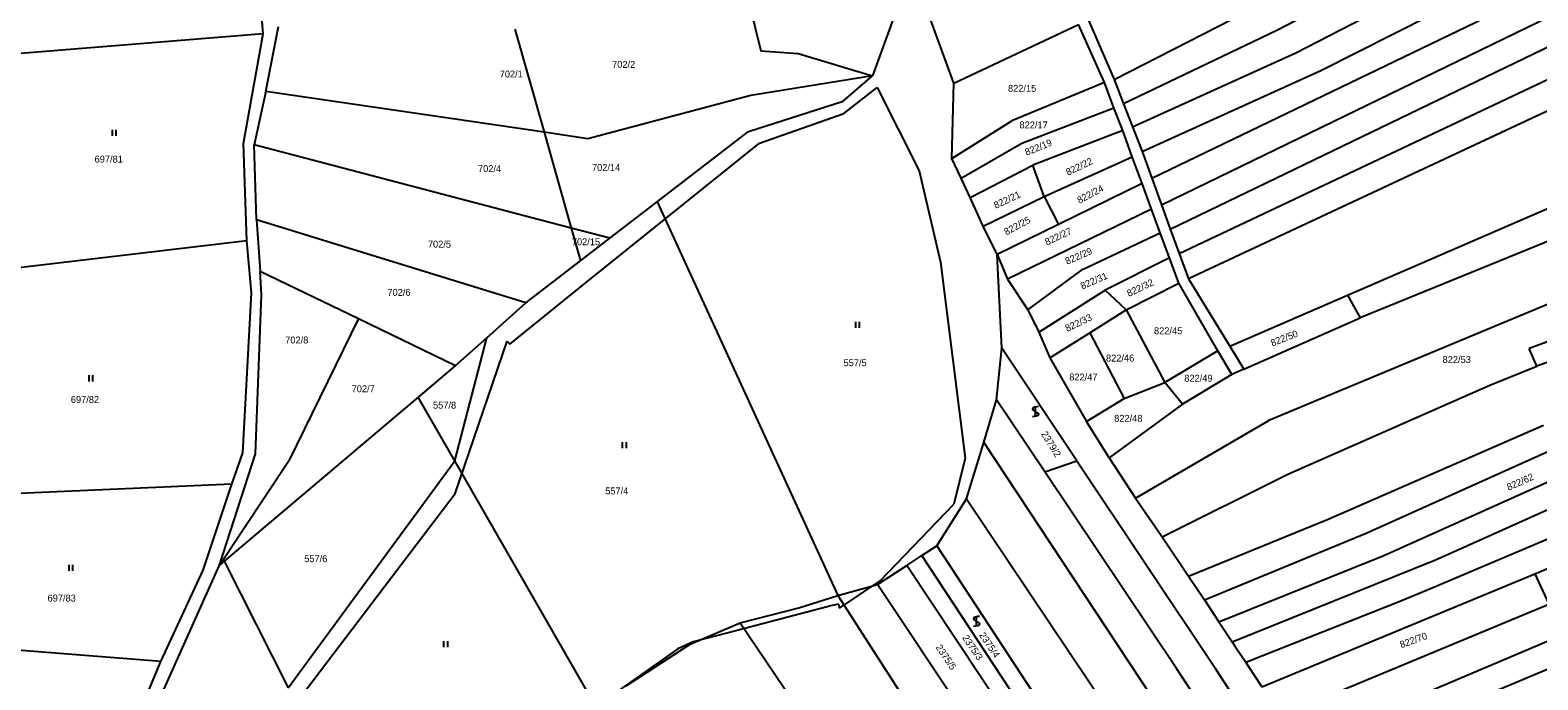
# Model space of a CAD drawing. Extents: x -580630 to -576196, y -1189024 to -1183567.
# Drawn here: x -577874.8 to -577503.9, y -1185181.6 to -1185021.8 of the extents above; entities that cross this region are included whole.
import ezdxf

# ---------------------------------------------------------------- set-up
doc = ezdxf.new("R2010")
doc.units = 0
for name, color, linetype in [('Vrstva 1', 7, 'Continuous'), ('Vrstva 18', 7, 'Continuous'), ('Vrstva 25', 7, 'Continuous'), ('Vrstva 5', 7, 'Continuous'), ('Vrstva 6', 7, 'Continuous')]:
    doc.layers.add(name, color=color, linetype=linetype)

msp = doc.modelspace()

# ---------------------------------------------------------------- linework, layer by layer
at = {"layer": 'Vrstva 1'}
for p, q in [((-577817.48, -1185022.68), (-577824.8, -1184925.19)), ((-577657.93, -1185006.49), (-577667.59, -1185033.06)), ((-577647.54, -1185034.82), (-577657.93, -1185006.49)), ((-577697.75, -1185015.88), (-577695.04, -1185026.88)), ((-577816.79, -1185036.88), (-577813.65, -1185020.88)), ((-577755.56, -1185021.6), (-577748.36, -1185046.94)), ((-577647.54, -1185034.82), (-577616.91, -1185020.39)), ((-577610.52, -1185034.7), (-577616.91, -1185020.39)), ((-577614.55, -1185019.21), (-577608.17, -1185033.92)), ((-577822.33, -1185049.67), (-577817.48, -1185022.68)), ((-577695.04, -1185026.88), (-577685.9, -1185027.59)), ((-577685.9, -1185027.59), (-577667.59, -1185033.06)), ((-577674.77, -1185039.3), (-577667.59, -1185033.06)), ((-577648.03, -1185053.37), (-577647.54, -1185034.82)), ((-577608.21, -1185040.89), (-577610.52, -1185034.7)), ((-577608.17, -1185033.92), (-577605.82, -1185039.92)), ((-577816.79, -1185036.88), (-577819.65, -1185050.02)), ((-577698.05, -1185046.74), (-577674.77, -1185039.3)), ((-577605.82, -1185039.92), (-577603.62, -1185045.55)), ((-577605.99, -1185046.52), (-577608.21, -1185040.89)), ((-577748.36, -1185046.94), (-577741.67, -1185070.48)), ((-577720.53, -1185064.02), (-577698.05, -1185046.74)), ((-577603.69, -1185052.97), (-577605.99, -1185046.52)), ((-577603.62, -1185045.55), (-577601.22, -1185051.68)), ((-577821.47, -1185073.67), (-577822.33, -1185049.67)), ((-577819.08, -1185068.45), (-577819.65, -1185050.02)), ((-577645.78, -1185058.23), (-577648.03, -1185053.37)), ((-577601.27, -1185059.54), (-577603.69, -1185052.97)), ((-577601.22, -1185051.68), (-577598.85, -1185058.24)), ((-577643.59, -1185062.96), (-577645.78, -1185058.23)), ((-577598.85, -1185058.24), (-577596.47, -1185064.81)), ((-577598.94, -1185065.88), (-577601.27, -1185059.54)), ((-577732.16, -1185072.97), (-577720.53, -1185064.02)), ((-577720.53, -1185064.02), (-577676.1, -1185160.83)), ((-577640.32, -1185070.01), (-577643.59, -1185062.96)), ((-577596.81, -1185071.68), (-577598.94, -1185065.88)), ((-577596.47, -1185064.81), (-577594.33, -1185070.72)), ((-577819.08, -1185068.45), (-577818.16, -1185081.09)), ((-577820.33, -1185086.38), (-577821.47, -1185073.67)), ((-577741.67, -1185070.48), (-577739.38, -1185078.52)), ((-577739.38, -1185078.52), (-577732.16, -1185072.97)), ((-577636.93, -1185077), (-577640.32, -1185070.01)), ((-577594.55, -1185077.82), (-577596.81, -1185071.68)), ((-577594.33, -1185070.72), (-577592.15, -1185076.73)), ((-577635.73, -1185100.04), (-577636.93, -1185077)), ((-577636.93, -1185077), (-577634.41, -1185083.02)), ((-577592.15, -1185076.73), (-577589.86, -1185082.96)), ((-577817.88, -1185086.95), (-577818.16, -1185081.09)), ((-577752.85, -1185088.87), (-577739.38, -1185078.52)), ((-577592.24, -1185084.08), (-577594.55, -1185077.82)), ((-577634.41, -1185083.02), (-577629.36, -1185090.63)), ((-577582.61, -1185100.66), (-577592.24, -1185084.08)), ((-577589.86, -1185082.96), (-577579.71, -1185099.57)), ((-577822.47, -1185125.79), (-577820.33, -1185086.38)), ((-577819.37, -1185126.01), (-577817.88, -1185086.95)), ((-577762.47, -1185097.46), (-577752.85, -1185088.87)), ((-577629.36, -1185090.63), (-577626.64, -1185096.08)), ((-577770.31, -1185127.75), (-577762.47, -1185097.46)), ((-577770.13, -1185104.3), (-577762.47, -1185097.46)), ((-577626.64, -1185096.08), (-577623.98, -1185102.4)), ((-577579.71, -1185099.57), (-577576.26, -1185105.21)), ((-577637.11, -1185112.76), (-577635.73, -1185100.04)), ((-577617.3, -1185127.71), (-577635.73, -1185100.04)), ((-577623.98, -1185102.4), (-577614.95, -1185118.04)), ((-577579.22, -1185106.49), (-577582.61, -1185100.66)), ((-577770.13, -1185104.3), (-577779.32, -1185112.07)), ((-577576.26, -1185105.21), (-577579.22, -1185106.49)), ((-577779.32, -1185112.07), (-577827.02, -1185152.42)), ((-577640.16, -1185123.2), (-577637.11, -1185112.76)), ((-577625.21, -1185130.49), (-577637.11, -1185112.76)), ((-577609.4, -1185126.98), (-577614.95, -1185118.04)), ((-577644.42, -1185137.13), (-577640.16, -1185123.2)), ((-577640.16, -1185123.2), (-577570.77, -1185228.3)), ((-577828.22, -1185153.43), (-577819.37, -1185126.01)), ((-577825.18, -1185133.5), (-577822.47, -1185125.79)), ((-577811.3, -1185183.62), (-577770.31, -1185127.75)), ((-577735.7, -1185187.98), (-577770.31, -1185127.75)), ((-577625.21, -1185130.49), (-577617.3, -1185127.71)), ((-577617.3, -1185127.71), (-577583.25, -1185178.84)), ((-577609.4, -1185126.98), (-577602.87, -1185136.95)), ((-577592.78, -1185178.81), (-577625.21, -1185130.49)), ((-577832.18, -1185154.64), (-577825.18, -1185133.5)), ((-577651.79, -1185148.64), (-577644.42, -1185137.13)), ((-577644.42, -1185137.13), (-577603.17, -1185198.62)), ((-577602.87, -1185136.95), (-577596.35, -1185146.43)), ((-577596.35, -1185146.43), (-577589.86, -1185156.13)), ((-577659.17, -1185153.47), (-577655.47, -1185151.05)), ((-577655.47, -1185151.05), (-577651.79, -1185148.64)), ((-577628.11, -1185192.49), (-577655.47, -1185151.05)), ((-577651.79, -1185148.64), (-577624.47, -1185190.27)), ((-577849.94, -1185202.01), (-577828.22, -1185153.43)), ((-577842.6, -1185177.07), (-577832.18, -1185154.64)), ((-577827.02, -1185152.42), (-577828.22, -1185153.43)), ((-577827.02, -1185152.42), (-577811.3, -1185183.62)), ((-577666.35, -1185158.17), (-577659.17, -1185153.47)), ((-577631.74, -1185194.7), (-577659.17, -1185153.47)), ((-577676.1, -1185160.83), (-577666.35, -1185158.17)), ((-577639.02, -1185199.14), (-577666.35, -1185158.17)), ((-577589.86, -1185156.13), (-577585.91, -1185161.95)), ((-577685.74, -1185163.88), (-577676.1, -1185160.83)), ((-577676.1, -1185160.83), (-577628.49, -1185234.92)), ((-577585.91, -1185161.95), (-577582.37, -1185167.31)), ((-577700.11, -1185167.62), (-577685.74, -1185163.88)), ((-577712.42, -1185172.85), (-577700.11, -1185167.62)), ((-577700.11, -1185167.62), (-577656.39, -1185232.42)), ((-577582.37, -1185167.31), (-577579.12, -1185172.23)), ((-577728.18, -1185183.09), (-577712.42, -1185172.85)), ((-577579.12, -1185172.23), (-577578.36, -1185173.38)), ((-577578.36, -1185173.38), (-577575.78, -1185177.3)), ((-577852.73, -1185201.2), (-577842.6, -1185177.07)), ((-577575.78, -1185177.3), (-577575.26, -1185178.09)), ((-577551.95, -1185240.94), (-577592.78, -1185178.81)), ((-577582.07, -1185180.64), (-577583.25, -1185178.84)), ((-577543.28, -1185239.79), (-577582.07, -1185180.64)), ((-577575.26, -1185178.09), (-577571.79, -1185183.35))]:
    msp.add_line(p, q, dxfattribs=at)
at = {"layer": 'Vrstva 25'}
for p, q in [((-577854.58, -1185046.31), (-577854.58, -1185047.81)), ((-577853.58, -1185047.81), (-577853.58, -1185046.31)), ((-577671.74, -1185093.53), (-577671.74, -1185095.03)), ((-577670.74, -1185095.03), (-577670.74, -1185093.53)), ((-577860.34, -1185106.69), (-577860.34, -1185108.19)), ((-577859.34, -1185108.19), (-577859.34, -1185106.69)), ((-577729.12, -1185123.16), (-577729.12, -1185124.66)), ((-577728.12, -1185124.66), (-577728.12, -1185123.16)), ((-577865.23, -1185153.31), (-577865.23, -1185154.81)), ((-577864.23, -1185154.81), (-577864.23, -1185153.31)), ((-577773.06, -1185172.1), (-577773.06, -1185173.6)), ((-577772.06, -1185173.6), (-577772.06, -1185172.1))]:
    msp.add_line(p, q, dxfattribs=at)
for points in [[(-577626.76, -1185114.42), (-577627.27, -1185114.48), (-577627.62, -1185114.53), (-577627.86, -1185114.61), (-577628.04, -1185114.72), (-577628.16, -1185114.81), (-577628.21, -1185114.98), (-577628.16, -1185115.21), (-577627.77, -1185115.53), (-577627.21, -1185115.84), (-577626.86, -1185116.11), (-577626.79, -1185116.31), (-577626.86, -1185116.51), (-577627.02, -1185116.64), (-577627.21, -1185116.71), (-577627.74, -1185116.84), (-577628.26, -1185116.91)], [(-577627.51, -1185116.92), (-577627.51, -1185115.65), (-577627.51, -1185114.42)], [(-577641.25, -1185166), (-577641.76, -1185166.06), (-577642.11, -1185166.11), (-577642.35, -1185166.19), (-577642.53, -1185166.3), (-577642.65, -1185166.39), (-577642.7, -1185166.56), (-577642.65, -1185166.79), (-577642.26, -1185167.11), (-577641.7, -1185167.42), (-577641.35, -1185167.69), (-577641.28, -1185167.89), (-577641.35, -1185168.09), (-577641.51, -1185168.22), (-577641.7, -1185168.29), (-577642.23, -1185168.42), (-577642.75, -1185168.49)], [(-577642, -1185168.5), (-577642, -1185167.23), (-577642, -1185166)]]:
    msp.add_lwpolyline(points, dxfattribs=at)
at = {"layer": 'Vrstva 5'}
for p, q in [((-577674.66, -1185042.33), (-577666.44, -1185035.89)), ((-577666.44, -1185035.89), (-577656.07, -1185056.41)), ((-577695.39, -1185049.57), (-577674.66, -1185042.33)), ((-577718.32, -1185068.07), (-577695.39, -1185049.57)), ((-577656.07, -1185056.41), (-577650.82, -1185078.87)), ((-577737.9, -1185083.79), (-577718.32, -1185068.07)), ((-577650.82, -1185078.87), (-577644.81, -1185127.06)), ((-577756.8, -1185099.06), (-577737.9, -1185083.79)), ((-577770.2, -1185135.76), (-577757.43, -1185098.28)), ((-577757.43, -1185098.28), (-577756.8, -1185099.06)), ((-577644.81, -1185127.06), (-577647.61, -1185138.38)), ((-577819.62, -1185200.7), (-577770.2, -1185135.76)), ((-577665.7, -1185157.23), (-577647.61, -1185138.38)), ((-577675.71, -1185163.96), (-577665.7, -1185157.23)), ((-577677.52, -1185163.36), (-577700.84, -1185169.44)), ((-577675.94, -1185162.99), (-577677.52, -1185163.36)), ((-577675.94, -1185162.99), (-577675.71, -1185163.96)), ((-577700.84, -1185169.44), (-577711.72, -1185172.3)), ((-577711.72, -1185172.3), (-577715.46, -1185174.01)), ((-577715.46, -1185174.01), (-577730.44, -1185184.6))]:
    msp.add_line(p, q, dxfattribs=at)
at = {"layer": 'Vrstva 6'}
for p, q in [((-577608.17, -1185033.92), (-577510.65, -1184984.04)), ((-577505.82, -1184989.47), (-577568.09, -1185021.87)), ((-577563.43, -1185027.4), (-577496.22, -1184992.64)), ((-577557.27, -1185031.76), (-577494.2, -1184999.76)), ((-577598.85, -1185058.24), (-577499.06, -1185010.09)), ((-577596.47, -1185064.81), (-577490.57, -1185013.35)), ((-577594.33, -1185070.72), (-577488.77, -1185019.82)), ((-577817.48, -1185022.68), (-577883.91, -1185028.07)), ((-577568.09, -1185021.87), (-577605.82, -1185039.92)), ((-577592.15, -1185076.73), (-577482.45, -1185024.93)), ((-577603.62, -1185045.55), (-577563.43, -1185027.4)), ((-577601.22, -1185051.68), (-577557.27, -1185031.76)), ((-577481.16, -1185032.13), (-577589.86, -1185082.96)), ((-577667.59, -1185033.06), (-577697.47, -1185037.87)), ((-577610.52, -1185034.7), (-577633.32, -1185044.09)), ((-577748.36, -1185046.94), (-577816.79, -1185036.88)), ((-577697.47, -1185037.87), (-577737.58, -1185048.52)), ((-577630.88, -1185049.63), (-577608.21, -1185040.89)), ((-577737.58, -1185048.52), (-577748.36, -1185046.94)), ((-577648.03, -1185053.37), (-577633.32, -1185044.09)), ((-577605.99, -1185046.52), (-577628.14, -1185055.02)), ((-577741.67, -1185070.48), (-577819.65, -1185050.02)), ((-577645.78, -1185058.23), (-577630.88, -1185049.63)), ((-577550.78, -1185087.02), (-577465.22, -1185049.89)), ((-577643.59, -1185062.96), (-577628.14, -1185055.02)), ((-577625.37, -1185062.72), (-577628.14, -1185055.02)), ((-577625.37, -1185062.72), (-577603.69, -1185052.97)), ((-577458.48, -1185056.14), (-577547.61, -1185092.61)), ((-577601.27, -1185059.54), (-577621.81, -1185069.6)), ((-577640.32, -1185070.01), (-577625.37, -1185062.72)), ((-577598.94, -1185065.88), (-577634.41, -1185083.02)), ((-577625.37, -1185062.72), (-577621.81, -1185069.6)), ((-577752.85, -1185088.87), (-577819.08, -1185068.45)), ((-577621.81, -1185069.6), (-577636.93, -1185077)), ((-577421.16, -1185069.1), (-577506.05, -1185100.12)), ((-577821.47, -1185073.67), (-577897.44, -1185082.6)), ((-577732.16, -1185072.97), (-577741.67, -1185070.48)), ((-577615.93, -1185080.7), (-577596.81, -1185071.68)), ((-577457.98, -1185071.16), (-577570.1, -1185117.79)), ((-577420.17, -1185074.14), (-577504.15, -1185104.44)), ((-577818.16, -1185081.09), (-577793.98, -1185092.77)), ((-577629.36, -1185090.63), (-577615.93, -1185080.7)), ((-577594.55, -1185077.82), (-577610.36, -1185085.76)), ((-577605.17, -1185090.6), (-577592.24, -1185084.08)), ((-577626.64, -1185096.08), (-577610.36, -1185085.76)), ((-577605.17, -1185090.6), (-577610.36, -1185085.76)), ((-577579.71, -1185099.57), (-577550.78, -1185087.02)), ((-577550.78, -1185087.02), (-577547.61, -1185092.61)), ((-577614.12, -1185096.22), (-577605.17, -1185090.6)), ((-577605.17, -1185090.6), (-577595.71, -1185108.46)), ((-577793.98, -1185092.77), (-577811.09, -1185127.58)), ((-577793.98, -1185092.77), (-577770.13, -1185104.3)), ((-577576.26, -1185105.21), (-577547.61, -1185092.61)), ((-577623.98, -1185102.4), (-577614.12, -1185096.22)), ((-577614.12, -1185096.22), (-577605.68, -1185112.41)), ((-577582.61, -1185100.66), (-577595.71, -1185108.46)), ((-577504.15, -1185104.44), (-577506.05, -1185100.12)), ((-577579.22, -1185106.49), (-577591.34, -1185113.79)), ((-577515.71, -1185109.11), (-577504.15, -1185104.44)), ((-577605.68, -1185112.41), (-577595.71, -1185108.46)), ((-577591.34, -1185113.79), (-577595.71, -1185108.46)), ((-577565.44, -1185131.03), (-577515.71, -1185109.11)), ((-577770.31, -1185127.75), (-577779.32, -1185112.07)), ((-577614.95, -1185118.04), (-577605.68, -1185112.41)), ((-577591.34, -1185113.79), (-577609.4, -1185126.98)), ((-577602.87, -1185136.95), (-577570.1, -1185117.79)), ((-577555.47, -1185142.09), (-577502.58, -1185118.99)), ((-577546.13, -1185145.56), (-577500.6, -1185125.03)), ((-577828.22, -1185153.43), (-577811.09, -1185127.58)), ((-577596.35, -1185146.43), (-577565.44, -1185131.03)), ((-577541.85, -1185151.01), (-577497.63, -1185131.16)), ((-577825.18, -1185133.5), (-577897.98, -1185136.64)), ((-577526.14, -1185150.81), (-577497.42, -1185137.93)), ((-577589.86, -1185156.13), (-577555.47, -1185142.09)), ((-577585.91, -1185161.95), (-577546.13, -1185145.56)), ((-577530.32, -1185159.12), (-577495.37, -1185144.31)), ((-577582.37, -1185167.31), (-577541.85, -1185151.01)), ((-577529.08, -1185152.13), (-577526.14, -1185150.81)), ((-577504.67, -1185155.5), (-577492.96, -1185150.64)), ((-577579.12, -1185172.23), (-577529.08, -1185152.13)), ((-577571.79, -1185183.35), (-577504.67, -1185155.5)), ((-577504.67, -1185155.5), (-577501.2, -1185162.98)), ((-577575.78, -1185177.3), (-577537.61, -1185162.21)), ((-577537.61, -1185162.21), (-577530.32, -1185159.12)), ((-577567.17, -1185190.35), (-577501.2, -1185162.98)), ((-577842.6, -1185177.07), (-577905.13, -1185172.23)), ((-577562.28, -1185197.76), (-577500.85, -1185171.8)), ((-577558.85, -1185202.96), (-577498.13, -1185177.53))]:
    msp.add_line(p, q, dxfattribs=at)

# ---------------------------------------------------------------- texts
at = {"layer": 'Vrstva 18'}
for s, p in [('702/1', (-577759.275, -1185033.45)), ('702/2', (-577731.627, -1185031.09)), ('822/15', (-577634.255, -1185036.97)), ('822/17', (-577631.428, -1185045.97)), ('697/81', (-577858.921, -1185054.38)), ('702/4', (-577764.613, -1185056.73)), ('702/14', (-577736.585, -1185056.44)), ('702/5', (-577776.94, -1185075.3)), ('702/15', (-577741.532, -1185074.71)), ('702/6', (-577786.883, -1185087.16)), ('822/45', (-577598.343, -1185096.61)), ('702/8', (-577812.024, -1185098.87)), ('557/5', (-577674.704, -1185104.47)), ('822/46', (-577610.146, -1185103.32)), ('822/53', (-577527.36, -1185103.67)), ('822/47', (-577619.186, -1185107.97)), ('822/49', (-577590.896, -1185108.27)), ('702/7', (-577795.693, -1185110.87)), ('697/82', (-577864.763, -1185113.51)), ('557/8', (-577775.677, -1185114.91)), ('822/48', (-577608.137, -1185118.14)), ('557/4', (-577733.327, -1185135.99)), ('557/6', (-577807.357, -1185152.66)), ('697/83', (-577870.486, -1185162.36))]:
    msp.add_text(s, height=1.7, dxfattribs=at).set_placement(p)
for s, rotation, p in [('822/19', 22.11617, (-577629.688, -1185052.717)), ('822/22', 25.43933, (-577619.523, -1185057.619)), ('822/21', 25.43933, (-577637.252, -1185065.788)), ('822/24', 28.13223, (-577616.694, -1185064.541)), ('822/25', 28.13223, (-577634.655, -1185072.313)), ('822/27', 25.21014, (-577624.688, -1185074.794)), ('822/29', 23.49127, (-577619.738, -1185079.532)), ('822/31', 23.49127, (-577615.971, -1185085.619)), ('822/32', 25.66851, (-577604.507, -1185087.451)), ('822/33', 25.66851, (-577619.679, -1185096.046)), ('822/50', 21.31403, (-577569.241, -1185099.628)), ('2379/2', 301.77687, (-577626.183, -1185121.12)), ('822/62', 24.06423, (-577511.12, -1185135.112)), ('2375/4', 304.126, (-577641.437, -1185170.629)), ('822/70', 19.82434, (-577537.499, -1185173.843)), ('2375/5', 304.126, (-577652.133, -1185173.63)), ('2375/3', 304.126, (-577645.596, -1185171.247))]:
    msp.add_text(s, height=1.7, rotation=rotation, dxfattribs=at).set_placement(p)

doc.saveas('drawing.dxf')
